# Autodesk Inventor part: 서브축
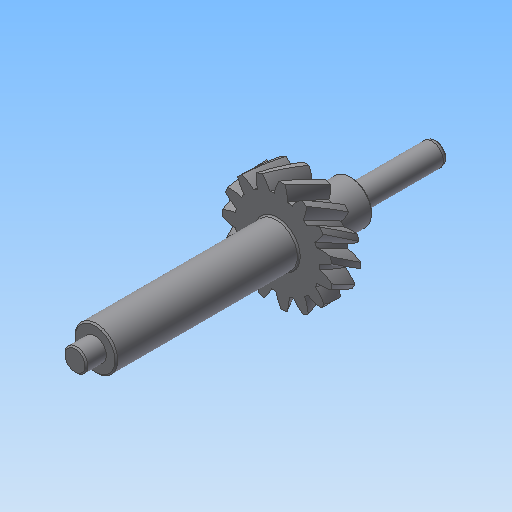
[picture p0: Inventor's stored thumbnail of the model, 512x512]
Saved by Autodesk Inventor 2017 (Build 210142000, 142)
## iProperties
Created: 2016-12
Part Number: 서브축
Material: 강철, 탄소
Document SubType Name: Modeling
Designer: mduedu
Categories: <?xml version="1.0" encoding="UTF-16"?> <MemberInstance><Categories><FamilyTemplate><FamilyTemplateParameter ValueType="xs:double" Id="1" ObjectReferenceKey="da
Density: 7.87 g/cm^3
Appearance: 기본값
Mass: 199.33 g
Surface Area: 86.8151 cm^2
Volume: 25.3278 cm^3
CustomPartVersion: 1
Author: mduedu
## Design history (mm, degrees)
sketch "Sketch1"
  geometry: C1 r 19.321 at (0, 0)
  constraints: 1 centre point
  dimensions: "d0" = 38.64102 diameter of C1 (= da_da)
extrude "Extrusion1" new body sketch "Sketch1" distance "d1" = 10 (= da_b); taper "d2" = 0 deg
workplane "Work Plane2"
sketch "Sketch2"
  geometry: C1 r 19.321 at (0, 0) reference; C2 r 17.321 at (0, 0)
  constraints: 1 centre point, 1 coincident
  dimensions: "d3" = 34.64102 diameter of C2 (= da_dw)
feature "피치 지름" sketch "Sketch2" dims "d4" = 10, "d5" = 0
workplane "Work Plane8"
workplane "Work Plane9"
feature "스퍼 기어" dims "d39" = 0, "da_b" = 10, "da_d" = 34.64102, "da_aw" = 43.87862, "da_da" = 38.64102, "da_df" = 29.64102, "da_dw" = 34.64102, angle "da_beta" = 30 deg, "da_lefttooth" = 0, "da_righttooth" = 10
sketch "스케치3"
  geometry: C1 r 7.5 at (0, 0); 1 further point
  constraints: 1 centre point, 1 coincident
  dimensions: "d49" = 15 diameter of C1
extrude "돌출2" join sketch "스케치3" distance "d50" = 64; taper "d51" = 0 deg
sketch "스케치4"
  geometry: C1 r 4 at (0, 0); 1 further point
  constraints: 1 centre point, 1 coincident
  dimensions: "d52" = 8 diameter of C1
extrude "돌출3" join sketch "스케치4" distance "d53" = 7; taper "d54" = 0 deg
sketch "스케치5"
  geometry: C1 r 7.5 at (0, 0) reference; 1 further point
extrude "돌출4" join sketch "스케치5" distance "d55" = 16; taper "d56" = 0 deg
sketch "스케치6"
  geometry: C1 r 4 at (0, 0); 1 further point
  constraints: 1 centre point, 1 coincident
  dimensions: "d57" = 8 diameter of C1
extrude "돌출5" join sketch "스케치6" distance "d58" = 30; taper "d59" = 0 deg
chamfer "모따기1" distance "d60" = 0.5; stored, may be unused: second distance "d61" = 2, angle "d62" = 45 deg
fillet "모깎기1" dims "d63" = 0.5
sketch "스케치7"
  geometry: L1 (-4, -46)-(4, -46) reference; L2 (4, -16)-(4, -46) reference; L3 (3.3, -46)-(4, -44.788); L4 (0, -46)-(0, 0)
  constraints: 4 end point, 2 point on line, 1 midpoint, 1 parallel
  dimensions: "d64" = 6.6 diameter of L3.start L4; "d65" = 30 deg angle of L2 L3
revolve "회전1" sketch "스케치7" stored, may be unused: angle "d66" = 90 deg
fillet "모깎기2" dims "d67" = 2, "d68" = 1
body "Solid1"
body "Srf1"
other parameters: "d16" = 43.87862 (= da_aw), "d17" = 0, "d34" = 12 deg (computed from da_z), "d41" = 0, "d43" = 43.87862 (= da_aw), "d46" = 43.87862 (= da_aw), "d47" = 0, "d48" = 0
